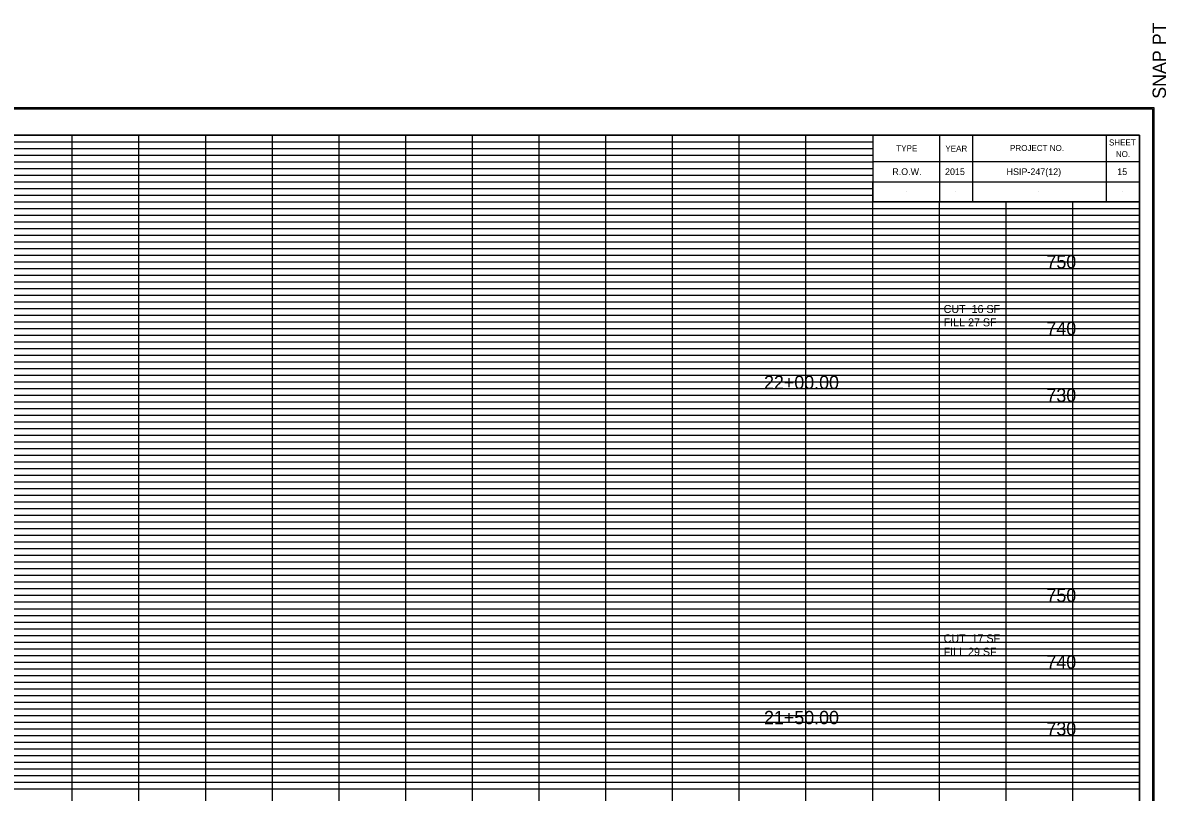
# Model space of a CAD drawing. Extents: x -200 to 1704, y -325 to 2307.
# Drawn here: x 1532.6 to 1704, y 1111.5 to 1226.8 of the extents above; entities that cross this region are included whole.
import ezdxf

# ---------------------------------------------------------------- set-up
doc = ezdxf.new("R2010")
doc.units = 0
for name, color, linetype in [('DESIGN - SCRATCH - User 1', 7, 'Continuous'), ('DESIGN - SHEET - Corner Text', 7, 'Continuous'), ('DESIGN - SHEET - Light Grid', 7, 'Continuous'), ('DESIGN - SHEET - Linework', 7, 'Continuous'), ('DESIGN - SHEET - Plot Shape', 7, 'Continuous'), ('DESIGN - TYPICAL - Text', 7, 'Continuous')]:
    doc.layers.add(name, color=color, linetype=linetype)

msp = doc.modelspace()

# ---------------------------------------------------------------- linework, layer by layer
at = {"layer": 'DESIGN - SCRATCH - User 1'}
for p, q in [((1665, 1204.5), (1665, 1204.5)), ((1672.4, 1204.5), (1672.4, 1204.5)), ((1684.9, 1204.5), (1684.9, 1204.5)), ((1697.4, 1204.5), (1697.4, 1204.5)), ((1665, 1201.5), (1665, 1201.5)), ((1672.4, 1201.5), (1672.4, 1201.5)), ((1684.9, 1201.5), (1684.9, 1201.5)), ((1697.4, 1201.5), (1697.4, 1201.5))]:
    msp.add_line(p, q, dxfattribs=at)
at = {"layer": 'DESIGN - SHEET - Light Grid'}
for p, q in [((1460, 1209), (1540, 1209)), ((1540, 1209), (1620, 1209)), ((1620, 1209), (1660, 1209)), ((1460, 1208), (1540, 1208)), ((1460, 1207), (1540, 1207)), ((1540, 1208), (1620, 1208)), ((1540, 1207), (1620, 1207)), ((1620, 1208), (1660, 1208)), ((1620, 1207), (1660, 1207)), ((1460, 1206), (1540, 1206)), ((1540, 1206), (1620, 1206)), ((1620, 1206), (1660, 1206)), ((1460, 1205), (1540, 1205)), ((1460, 1204), (1540, 1204)), ((1540, 1205), (1620, 1205)), ((1540, 1204), (1620, 1204)), ((1620, 1205), (1660, 1205)), ((1620, 1204), (1660, 1204)), ((1460, 1203), (1540, 1203)), ((1460, 1202), (1540, 1202)), ((1540, 1203), (1620, 1203)), ((1540, 1202), (1620, 1202)), ((1620, 1203), (1660, 1203)), ((1620, 1202), (1660, 1202)), ((1460, 1201), (1540, 1201)), ((1540, 1201), (1620, 1201)), ((1620, 1201), (1660, 1201)), ((1460, 1199), (1540, 1199)), ((1540, 1199), (1620, 1199)), ((1620, 1199), (1700, 1199)), ((1460, 1198), (1540, 1198)), ((1460, 1197), (1540, 1197)), ((1540, 1198), (1620, 1198)), ((1540, 1197), (1620, 1197)), ((1620, 1198), (1700, 1198)), ((1620, 1197), (1700, 1197)), ((1460, 1196), (1540, 1196)), ((1460, 1195), (1540, 1195)), ((1540, 1196), (1620, 1196)), ((1540, 1195), (1620, 1195)), ((1620, 1196), (1700, 1196)), ((1620, 1195), (1700, 1195)), ((1460, 1194), (1540, 1194)), ((1540, 1194), (1620, 1194)), ((1620, 1194), (1700, 1194)), ((1460, 1193), (1540, 1193)), ((1460, 1192), (1540, 1192)), ((1540, 1193), (1620, 1193)), ((1540, 1192), (1620, 1192)), ((1620, 1193), (1700, 1193)), ((1620, 1192), (1700, 1192)), ((1460, 1191), (1540, 1191)), ((1540, 1191), (1620, 1191)), ((1620, 1191), (1700, 1191)), ((1460, 1189), (1540, 1189)), ((1460, 1188), (1540, 1188)), ((1540, 1189), (1620, 1189)), ((1540, 1188), (1620, 1188)), ((1620, 1189), (1700, 1189)), ((1620, 1188), (1700, 1188)), ((1460, 1187), (1540, 1187)), ((1540, 1187), (1620, 1187)), ((1620, 1187), (1700, 1187)), ((1460, 1186), (1540, 1186)), ((1460, 1185), (1540, 1185)), ((1540, 1186), (1620, 1186)), ((1540, 1185), (1620, 1185)), ((1620, 1186), (1700, 1186)), ((1620, 1185), (1700, 1185)), ((1460, 1184), (1540, 1184)), ((1460, 1183), (1540, 1183)), ((1540, 1184), (1620, 1184)), ((1540, 1183), (1620, 1183)), ((1620, 1184), (1700, 1184)), ((1620, 1183), (1700, 1183)), ((1460, 1182), (1540, 1182)), ((1540, 1182), (1620, 1182)), ((1620, 1182), (1700, 1182)), ((1460, 1181), (1540, 1181)), ((1540, 1181), (1620, 1181)), ((1620, 1181), (1700, 1181)), ((1460, 1179), (1540, 1179)), ((1460, 1178), (1540, 1178)), ((1540, 1179), (1620, 1179)), ((1540, 1178), (1620, 1178)), ((1620, 1179), (1700, 1179)), ((1620, 1178), (1700, 1178)), ((1460, 1177), (1540, 1177)), ((1460, 1176), (1540, 1176)), ((1540, 1177), (1620, 1177)), ((1540, 1176), (1620, 1176)), ((1620, 1177), (1700, 1177)), ((1620, 1176), (1700, 1176)), ((1460, 1175), (1540, 1175)), ((1540, 1175), (1620, 1175)), ((1620, 1175), (1700, 1175)), ((1460, 1174), (1540, 1174)), ((1460, 1173), (1540, 1173)), ((1540, 1174), (1620, 1174)), ((1540, 1173), (1620, 1173)), ((1620, 1174), (1700, 1174)), ((1620, 1173), (1700, 1173)), ((1460, 1172), (1540, 1172)), ((1460, 1171), (1540, 1171)), ((1540, 1172), (1620, 1172)), ((1540, 1171), (1620, 1171)), ((1620, 1172), (1700, 1172)), ((1620, 1171), (1700, 1171)), ((1460, 1169), (1540, 1169)), ((1460, 1168), (1540, 1168)), ((1540, 1169), (1620, 1169)), ((1540, 1168), (1620, 1168)), ((1620, 1169), (1700, 1169)), ((1620, 1168), (1700, 1168)), ((1460, 1167), (1540, 1167)), ((1460, 1166), (1540, 1166)), ((1540, 1167), (1620, 1167)), ((1540, 1166), (1620, 1166)), ((1620, 1167), (1700, 1167)), ((1620, 1166), (1700, 1166)), ((1460, 1165), (1540, 1165)), ((1460, 1164), (1540, 1164)), ((1540, 1165), (1620, 1165)), ((1540, 1164), (1620, 1164)), ((1620, 1165), (1700, 1165)), ((1620, 1164), (1700, 1164)), ((1460, 1163), (1540, 1163)), ((1540, 1163), (1620, 1163)), ((1620, 1163), (1700, 1163)), ((1460, 1162), (1540, 1162)), ((1460, 1161), (1540, 1161)), ((1540, 1162), (1620, 1162)), ((1540, 1161), (1620, 1161)), ((1620, 1162), (1700, 1162)), ((1620, 1161), (1700, 1161)), ((1460, 1159), (1540, 1159)), ((1540, 1159), (1620, 1159)), ((1620, 1159), (1700, 1159)), ((1460, 1158), (1540, 1158)), ((1540, 1158), (1620, 1158)), ((1620, 1158), (1700, 1158)), ((1460, 1157), (1540, 1157)), ((1460, 1156), (1540, 1156)), ((1540, 1157), (1620, 1157)), ((1540, 1156), (1620, 1156)), ((1620, 1157), (1700, 1157)), ((1620, 1156), (1700, 1156)), ((1460, 1155), (1540, 1155)), ((1460, 1154), (1540, 1154)), ((1540, 1155), (1620, 1155)), ((1540, 1154), (1620, 1154)), ((1620, 1155), (1700, 1155)), ((1620, 1154), (1700, 1154)), ((1460, 1153), (1540, 1153)), ((1460, 1152), (1540, 1152)), ((1540, 1153), (1620, 1153)), ((1540, 1152), (1620, 1152)), ((1620, 1153), (1700, 1153)), ((1620, 1152), (1700, 1152)), ((1460, 1151), (1540, 1151)), ((1540, 1151), (1620, 1151)), ((1620, 1151), (1700, 1151)), ((1460, 1149), (1540, 1149)), ((1540, 1149), (1620, 1149)), ((1620, 1149), (1700, 1149)), ((1460, 1148), (1540, 1148)), ((1460, 1147), (1540, 1147)), ((1540, 1148), (1620, 1148)), ((1540, 1147), (1620, 1147)), ((1620, 1148), (1700, 1148)), ((1620, 1147), (1700, 1147)), ((1460, 1146), (1540, 1146)), ((1540, 1146), (1620, 1146)), ((1620, 1146), (1700, 1146)), ((1460, 1145), (1540, 1145)), ((1460, 1144), (1540, 1144)), ((1540, 1145), (1620, 1145)), ((1540, 1144), (1620, 1144)), ((1620, 1145), (1700, 1145)), ((1620, 1144), (1700, 1144)), ((1460, 1143), (1540, 1143)), ((1460, 1142), (1540, 1142)), ((1540, 1143), (1620, 1143)), ((1540, 1142), (1620, 1142)), ((1620, 1143), (1700, 1143)), ((1620, 1142), (1700, 1142)), ((1460, 1141), (1540, 1141)), ((1540, 1141), (1620, 1141)), ((1620, 1141), (1700, 1141)), ((1460, 1139), (1540, 1139)), ((1540, 1139), (1620, 1139)), ((1620, 1139), (1700, 1139)), ((1460, 1138), (1540, 1138)), ((1460, 1137), (1540, 1137)), ((1540, 1138), (1620, 1138)), ((1540, 1137), (1620, 1137)), ((1620, 1138), (1700, 1138)), ((1620, 1137), (1700, 1137)), ((1460, 1136), (1540, 1136)), ((1460, 1135), (1540, 1135)), ((1540, 1136), (1620, 1136)), ((1540, 1135), (1620, 1135)), ((1620, 1136), (1700, 1136)), ((1620, 1135), (1700, 1135)), ((1460, 1134), (1540, 1134)), ((1540, 1134), (1620, 1134)), ((1620, 1134), (1700, 1134)), ((1460, 1133), (1540, 1133)), ((1460, 1132), (1540, 1132)), ((1540, 1133), (1620, 1133)), ((1540, 1132), (1620, 1132)), ((1620, 1133), (1700, 1133)), ((1620, 1132), (1700, 1132)), ((1460, 1131), (1540, 1131)), ((1540, 1131), (1620, 1131)), ((1620, 1131), (1700, 1131)), ((1460, 1129), (1540, 1129)), ((1460, 1128), (1540, 1128)), ((1540, 1129), (1620, 1129)), ((1540, 1128), (1620, 1128)), ((1620, 1129), (1700, 1129)), ((1620, 1128), (1700, 1128)), ((1460, 1127), (1540, 1127)), ((1540, 1127), (1620, 1127)), ((1620, 1127), (1700, 1127)), ((1460, 1126), (1540, 1126)), ((1460, 1125), (1540, 1125)), ((1540, 1126), (1620, 1126)), ((1540, 1125), (1620, 1125)), ((1620, 1126), (1700, 1126)), ((1620, 1125), (1700, 1125)), ((1460, 1124), (1540, 1124)), ((1460, 1123), (1540, 1123)), ((1540, 1124), (1620, 1124)), ((1540, 1123), (1620, 1123)), ((1620, 1124), (1700, 1124)), ((1620, 1123), (1700, 1123)), ((1460, 1122), (1540, 1122)), ((1540, 1122), (1620, 1122)), ((1620, 1122), (1700, 1122)), ((1460, 1121), (1540, 1121)), ((1540, 1121), (1620, 1121)), ((1620, 1121), (1700, 1121)), ((1460, 1119), (1540, 1119)), ((1460, 1118), (1540, 1118)), ((1540, 1119), (1620, 1119)), ((1540, 1118), (1620, 1118)), ((1620, 1119), (1700, 1119)), ((1620, 1118), (1700, 1118)), ((1460, 1117), (1540, 1117)), ((1460, 1116), (1540, 1116)), ((1540, 1117), (1620, 1117)), ((1540, 1116), (1620, 1116)), ((1620, 1117), (1700, 1117)), ((1620, 1116), (1700, 1116)), ((1460, 1115), (1540, 1115)), ((1540, 1115), (1620, 1115)), ((1620, 1115), (1700, 1115)), ((1460, 1114), (1540, 1114)), ((1460, 1113), (1540, 1113)), ((1540, 1114), (1620, 1114)), ((1540, 1113), (1620, 1113)), ((1620, 1114), (1700, 1114)), ((1620, 1113), (1700, 1113)), ((1460, 1112), (1540, 1112)), ((1540, 1112), (1620, 1112)), ((1620, 1112), (1700, 1112))]:
    msp.add_line(p, q, dxfattribs=at)
at = {"layer": 'DESIGN - SHEET - Linework'}
for p, q in [((1361.77, 1214.14), (1702.17, 1214.14)), ((1702.17, 1214.14), (1702.17, 995.86)), ((1540, 1000), (1540, 1210)), ((1550, 1000), (1550, 1210)), ((1560, 1000), (1560, 1210)), ((1570, 1000), (1570, 1210)), ((1580, 1000), (1580, 1210)), ((1590, 1000), (1590, 1210)), ((1600, 1000), (1600, 1210)), ((1610, 1000), (1610, 1210)), ((1620, 1000), (1620, 1210)), ((1630, 1000), (1630, 1210)), ((1640, 1000), (1640, 1210)), ((1650, 1000), (1650, 1210)), ((1380, 1200), (1660, 1200)), ((1660, 1000), (1660, 1200)), ((1670, 1000), (1670, 1200)), ((1680, 1000), (1680, 1200)), ((1690, 1000), (1690, 1200)), ((1380, 1190), (1700, 1190)), ((1380, 1180), (1700, 1180)), ((1380, 1170), (1700, 1170)), ((1380, 1160), (1700, 1160)), ((1380, 1150), (1700, 1150)), ((1380, 1140), (1700, 1140)), ((1380, 1130), (1700, 1130)), ((1380, 1120), (1700, 1120))]:
    msp.add_line(p, q, dxfattribs=at)
for points in [[(1380, 1210), (1380, 1000), (1700, 1000), (1700, 1210), (1380, 1210)], [(1660, 1210), (1660, 1200), (1700, 1200), (1700, 1210), (1695, 1210), (1695, 1200), (1675, 1200), (1675, 1210), (1670, 1210), (1670, 1200), (1700, 1200), (1660, 1200), (1660, 1203), (1700, 1203), (1700, 1206), (1660, 1206)]]:
    msp.add_lwpolyline(points, dxfattribs=at)
at = {"layer": 'DESIGN - SHEET - Plot Shape'}
for points in [[(1361.97, 1213.94), (1701.97, 1213.94), (1701.97, 996.06), (1361.97, 996.06)], [(1371.5, 1210), (1700, 1210), (1700, 997.5), (1371.5, 997.5)]]:
    msp.add_lwpolyline(points, close=True, dxfattribs=at)

# ---------------------------------------------------------------- texts
at = {"layer": 'DESIGN - SHEET - Corner Text'}
msp.add_text('  SNAP PT', height=2, rotation=90, dxfattribs=at).set_placement((1703.97, 1213.94))
for s, height, p in [('TYPE', 0.9, (1663.54, 1207.56)), ('PROJECT NO.', 0.9, (1680.6, 1207.6)), ('SHEET', 0.9, (1695.43, 1208.43)), ('YEAR', 0.9, (1670.9, 1207.52)), ('NO.', 0.9, (1696.46, 1206.69)), ('R.O.W.', 1, (1662.94, 1204)), ('2015', 1, (1670.85, 1204)), ('HSIP-247(12)', 1, (1680.08, 1204)), ('15', 1, (1696.67, 1204))]:
    msp.add_text(s, height=height, dxfattribs=at).set_placement(p)
at = {"layer": 'DESIGN - TYPICAL - Text'}
for s, height, p in [('     750     ', 2, (1682.34, 1190)), ('CUT  16 SF', 1.2, (1670.64, 1183.32)), ('FILL 27 SF', 1.2, (1670.64, 1181.32)), ('     740     ', 2, (1682.34, 1180)), ('     22+00.00     ', 2, (1640, 1171.92)), ('     730     ', 2, (1682.34, 1170)), ('     750     ', 2, (1682.34, 1140)), ('CUT  17 SF', 1.2, (1670.64, 1133.94)), ('FILL 29 SF', 1.2, (1670.64, 1131.94)), ('     740     ', 2, (1682.34, 1130)), ('     21+50.00     ', 2, (1640, 1121.68)), ('     730     ', 2, (1682.34, 1120))]:
    msp.add_text(s, height=height, dxfattribs=at).set_placement(p)

doc.saveas('drawing.dxf')
